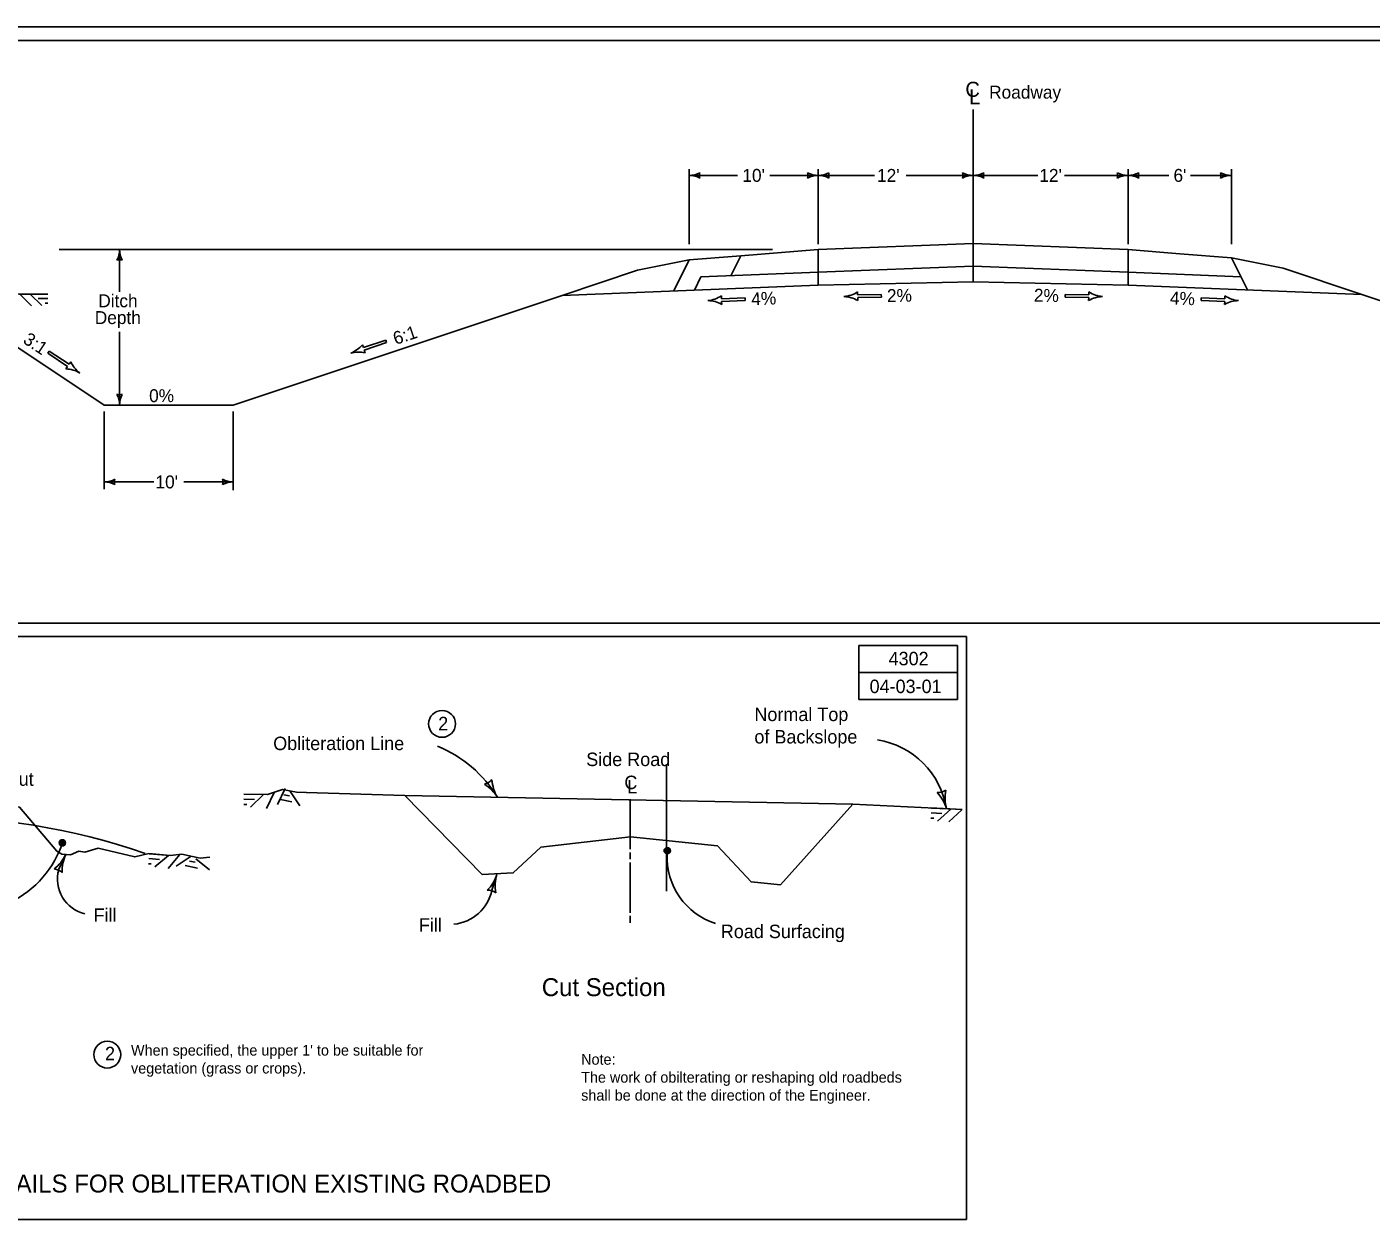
# Model space of a CAD drawing. Extents: x 4574 to 81668, y 5908 to 13780.
# Drawn here: x 10645 to 12144, y 8607 to 9944 of the extents above; entities that cross this region are included whole.
import ezdxf

# ---------------------------------------------------------------- set-up
doc = ezdxf.new("R2010")
doc.units = 0
for name, color, linetype in [('Cell', 7, 'Continuous'), ('dsnCellElements', 7, 'Continuous'), ('DsnShtRevisedText', 7, 'Continuous'), ('dsnStdBorder', 7, 'Continuous'), ('dsnStdLabel', 7, 'Continuous'), ('dsnStdNameDate', 7, 'Continuous'), ('dsnTextFinalPlan', 7, 'Continuous'), ('dsnTextTabulation', 7, 'Continuous'), ('dsnXsExistingGround', 7, 'Continuous'), ('dsnXsShldrGranularBottom', 7, 'Continuous'), ('dsnXsShldrHMABottom', 7, 'Continuous'), ('dsnXsShldrSpecialBackBottom', 7, 'Continuous'), ('dsnXsSubgrPara', 7, 'Continuous'), ('Level 11', 7, 'Continuous'), ('Level 6', 7, 'Continuous'), ('Level 7', 7, 'Continuous'), ('Level 8', 7, 'Continuous'), ('SheetAddendum', 7, 'Continuous'), ('SheetBorder', 7, 'Continuous'), ('ShtPlotIdentification', 7, 'Continuous'), ('TL_ExistingPvmtBtm', 7, 'Continuous'), ('TL_ExistingPvmtTop', 7, 'Continuous')]:
    doc.layers.add(name, color=color, linetype=linetype)

msp = doc.modelspace()

# ---------------------------------------------------------------- linework, layer by layer
at = {"layer": 'Cell'}
for p, q in [((11325.7, 9672.5), (11241.8, 9644.6)), ((11383.3, 9684.1), (11325.7, 9672.5)), ((11241.8, 9644.6), (10874.9, 9522.2)), ((12133.5, 9645.5), (12285.8, 9594.8)), ((10730.9, 9522.2), (10559, 9636.8)), ((10874.9, 9522.2), (10730.9, 9522.2))]:
    msp.add_line(p, q, dxfattribs=at)
at = {"layer": 'dsnCellElements'}
for p, q in [((11358, 9121.6), (11358, 8980.1)), ((10680.1, 9003.9), (10688, 9021)), ((11163.3, 8981.1), (11168.8, 8998.8))]:
    msp.add_line(p, q, dxfattribs=at)
for points in [[(10886.8, 9088.1), (10913.2, 9087.8), (10929.8, 9093.5), (10945.5, 9090.4), (10956, 9090.1)], [(10886.8, 9088.1), (10913.2, 9087.8), (10929.8, 9093.5), (10945.5, 9090.4), (10956.5, 9090.1)], [(10886.8, 9088.1), (10913.2, 9087.8), (10929.8, 9093.5), (10945.5, 9090.4), (10954.8, 9090.1)], [(10956, 9090.1), (11066, 9086.7), (11152.4, 8998.5), (11187.1, 9000.5), (11217.9, 9029), (11317.8, 9040.7), (11414.7, 9030.8), (11452.3, 8990.4), (11485.2, 8987.3), (11565.8, 9077.3), (11687.7, 9071.1)], [(10267.7, 9010.1), (10268.5, 9010.6), (10279.4, 9008.9), (10318.4, 9017.9), (10338, 9011), (10384.6, 9020), (10443.1, 9071.5), (10537.4, 9080.9), (10636.5, 9073.7), (10678.1, 9024.7), (10683.8, 9021.3), (10693.5, 9020.7), (10702.5, 9024.7), (10709.2, 9023.7), (10724, 9028.2), (10764.9, 9018.3), (10780.5, 9022), (10780.7, 9021.9)], [(11681.2, 9071.4), (11652.3, 9072.9)], [(11681.2, 9071.4), (11653.5, 9072.8)], [(11653.5, 9072.8), (11681.2, 9071.4)], [(10780.5, 9022), (10804.3, 9019.9), (10817.4, 9021.2), (10838, 9016.8), (10848.7, 9017.9)], [(10781.1, 9021.9), (10804.3, 9019.9), (10817.4, 9021.2), (10838, 9016.8), (10848.7, 9017.9)]]:
    msp.add_lwpolyline(points, dxfattribs=at)
at = {"layer": 'DsnShtRevisedText'}
msp.add_line((11066, 9086.7), (11565.8, 9077.3), dxfattribs=at)
for points in [[(11317.4, 9082.7), (11317.4, 9026.9)], [(11317.4, 9023.1), (11317.4, 9015.7)], [(11317.4, 9012), (11317.4, 8956.1)], [(11317.4, 8952.4), (11317.4, 8944.9)]]:
    msp.add_lwpolyline(points, dxfattribs=at)
for centre, radius, start, end in [((10539.4, 8343.7), 718.7, 70.7273, 111.6141), ((11436.5, 9018), 77.8, 174.663, 174.8906)]:
    msp.add_arc(centre, radius, start, end, dxfattribs=at)
at = {"layer": 'dsnStdBorder'}
msp.add_lwpolyline([(10147.5, 9929), (13252.5, 9929), (13252.5, 9279), (10147.5, 9279), (10147.5, 9929)], dxfattribs=at)
at = {"layer": 'dsnStdLabel'}
for p, q in [((11419.3, 9644.1), (11419.4, 9640.8)), ((11419.4, 9640.8), (11445.8, 9641.8)), ((11445.8, 9641.8), (11445.9, 9638.9)), ((11555.8, 9643.3), (11555.8, 9643.3)), ((11571.1, 9648.4), (11571.1, 9645)), ((11571.1, 9645), (11597.5, 9645.6)), ((11597.6, 9642.7), (11571.2, 9642.1)), ((11571.2, 9642.1), (11571.2, 9638.8)), ((11597.5, 9645.6), (11597.6, 9642.7)), ((11828.9, 9645), (11802.5, 9645.6)), ((11802.5, 9645.6), (11802.5, 9642.7)), ((11802.5, 9642.7), (11828.9, 9642.1)), ((11828.9, 9642.1), (11828.8, 9638.8)), ((11829, 9648.4), (11828.9, 9645)), ((11844.2, 9643.3), (11844.2, 9643.3)), ((11954.3, 9641.8), (11954.2, 9638.9)), ((11980.7, 9640.8), (11954.3, 9641.8)), ((11980.8, 9644.1), (11980.7, 9640.8)), ((11404.2, 9638.7), (11404.2, 9638.7)), ((11445.9, 9638.9), (11419.5, 9637.9)), ((11419.5, 9637.9), (11419.6, 9634.5)), ((11954.2, 9638.9), (11980.5, 9637.9)), ((11980.5, 9637.9), (11980.4, 9634.5)), ((11995.9, 9638.7), (11995.9, 9638.7)), ((11019.9, 9586.4), (11045, 9594.7)), ((11045, 9594.7), (11045.9, 9592)), ((10669.7, 9582.4), (10668.1, 9580)), ((10668.1, 9580), (10690.1, 9565.4)), ((10691.7, 9567.8), (10669.7, 9582.4)), ((11005.9, 9580.1), (11005.9, 9580.1)), ((11018.9, 9589.5), (11019.9, 9586.4)), ((11045.9, 9592), (11020.8, 9583.6)), ((11020.8, 9583.6), (11021.9, 9580.4)), ((10690.1, 9565.4), (10688.2, 9562.6)), ((10693.6, 9570.6), (10691.7, 9567.8)), ((10703.6, 9558.1), (10703.6, 9558.1))]:
    msp.add_line(p, q, dxfattribs=at)
for centre, start, end in [((11401.6, 9669.6), 274.6426, 304.6726), ((11554, 9674.2), 273.4978, 303.5278), ((11555.2, 9612.3), 58.7638, 88.7938), ((11844.8, 9612.3), 91.2062, 121.2362), ((11846.1, 9674.2), 236.4722, 266.5022), ((11998.4, 9669.6), 235.3274, 265.3574), ((11404.1, 9607.8), 59.9086, 89.9386), ((11995.9, 9607.8), 90.0614, 120.0914), ((10994.9, 9609.1), 290.787, 320.817), ((11014.4, 9550.4), 76.053, 106.083), ((10721.8, 9583.1), 203.9305, 233.9606), ((10687.5, 9531.6), 58.6646, 88.6946)]:
    msp.add_arc(centre, 30.9, start, end, dxfattribs=at)
at = {"layer": 'dsnStdNameDate'}
for p, q in [((11527.2, 9656), (11527.2, 9695.6)), ((11872.8, 9695.6), (11872.8, 9656))]:
    msp.add_line(p, q, dxfattribs=at)
at = {"layer": 'dsnTextFinalPlan'}
for p, q in [((11700, 9659.6), (11700, 9851.7)), ((11383.3, 9785.4), (11383.3, 9701.8)), ((11437.3, 9778.4), (11383.3, 9778.4)), ((11527.2, 9778.4), (11473.3, 9778.4)), ((11527.2, 9785.4), (11527.2, 9701.8)), ((11589.8, 9778.4), (11527.2, 9778.4)), ((11700, 9778.4), (11625.1, 9778.4)), ((11772.3, 9778.4), (11700, 9778.4)), ((11872.8, 9778.4), (11801.8, 9778.4)), ((11872.8, 9785.4), (11872.8, 9701.8)), ((11912.4, 9778.4), (11872.8, 9778.4)), ((11912.4, 9778.4), (11918.4, 9778.4)), ((11948.4, 9778.4), (11942.4, 9778.4)), ((11988, 9778.4), (11948.4, 9778.4)), ((11988, 9785.4), (11988, 9701.8)), ((10680.6, 9695.7), (11476.1, 9695.7)), ((10748.1, 9648.7), (10748.1, 9695.7)), ((10748.1, 9522.2), (10748.1, 9604)), ((10730.9, 9515), (10730.9, 9428.4)), ((10874.9, 9515), (10874.9, 9427.5)), ((10786.1, 9436.5), (10730.9, 9436.5)), ((10874.9, 9436.5), (10819.7, 9436.5))]:
    msp.add_line(p, q, dxfattribs=at)
for centre, radius, start, end in [((11383.3, 9803.9), 25.5, 270, 298.0725), ((11383.3, 9752.9), 25.5, 61.9275, 90), ((11404.7, 9778.4), 9.85, 162.2666, 197.7334), ((11505.9, 9778.4), 9.85, 342.2667, 17.7334), ((11527.2, 9803.9), 25.5, 241.9275, 270), ((11527.2, 9752.9), 25.5, 90, 118.0725), ((11527.2, 9803.9), 25.5, 270, 298.0725), ((11527.2, 9752.9), 25.5, 61.9275, 90), ((11548.6, 9778.4), 9.85, 162.2666, 197.7334), ((11678.6, 9778.4), 9.85, 342.2667, 17.7334), ((11700, 9803.9), 25.5, 241.9275, 270), ((11700, 9752.9), 25.5, 90, 118.0725), ((11700, 9803.9), 25.5, 270, 298.0725), ((11700, 9752.9), 25.5, 61.9275, 90), ((11721.4, 9778.4), 9.85, 162.2666, 197.7334), ((11851.4, 9778.4), 9.85, 342.2667, 17.7334), ((11872.8, 9803.9), 25.5, 241.9275, 270), ((11872.8, 9752.9), 25.5, 90, 118.0725), ((11872.8, 9803.9), 25.5, 270, 298.0725), ((11872.8, 9752.9), 25.5, 61.9275, 90), ((11894.2, 9778.4), 9.85, 162.2666, 197.7334), ((11966.6, 9778.4), 9.85, 342.2667, 17.7334), ((11988, 9803.9), 25.5, 241.9275, 270), ((11988, 9752.9), 25.5, 90, 118.0725), ((10722.6, 9695.7), 25.5, 331.9275, 360), ((10773.6, 9695.7), 25.5, 180, 208.0725), ((10748.1, 9674.3), 9.85, 72.2666, 107.7334), ((10748.1, 9543.6), 9.85, 252.2666, 287.7334), ((10722.6, 9522.2), 25.5, 360, 28.0725), ((10773.6, 9522.2), 25.5, 151.9275, 180), ((10730.9, 9462), 25.5, 270, 298.0725), ((10730.9, 9411), 25.5, 61.9275, 90), ((10752.3, 9436.5), 9.85, 162.2666, 197.7334), ((10853.5, 9436.5), 9.85, 342.2666, 17.7334), ((10874.9, 9462), 25.5, 241.9275, 270), ((10874.9, 9411), 25.5, 90, 118.0725)]:
    msp.add_arc(centre, radius, start, end, dxfattribs=at)
at = {"layer": 'dsnXsExistingGround'}
for p, q in [((10637.2, 9645.6), (10650, 9633)), ((10648.4, 9645.9), (10661.2, 9633.3))]:
    msp.add_line(p, q, dxfattribs=at)
for points in [[(10667.9, 9646), (10636, 9645.8), (10604.2, 9646.8), (10557.3, 9650), (10510.6, 9655)], [(10667.9, 9641.1), (10657.1, 9641)], [(10667.9, 9635.9), (10665, 9635.9)]]:
    msp.add_lwpolyline(points, dxfattribs=at)
at = {"layer": 'dsnXsShldrGranularBottom'}
for p, q in [((11988, 9686.4), (12005.9, 9650.7)), ((11383.3, 9684.1), (11366, 9649.5))]:
    msp.add_line(p, q, dxfattribs=at)
at = {"layer": 'dsnXsShldrHMABottom'}
msp.add_line((11440.9, 9688.7), (11429.8, 9666.5), dxfattribs=at)
at = {"layer": 'dsnXsShldrSpecialBackBottom'}
msp.add_line((11396.4, 9665.1), (11389.1, 9650.4), dxfattribs=at)
at = {"layer": 'dsnXsSubgrPara'}
for p, q in [((11527.2, 9656), (11241.8, 9644.6)), ((11872.8, 9656), (12133.5, 9645.5))]:
    msp.add_line(p, q, dxfattribs=at)
msp.add_lwpolyline([(11527.2, 9656), (11700, 9659.6), (11872.8, 9656)], dxfattribs=at)
at = {"layer": 'Level 11'}
msp.add_lwpolyline([(11682.5, 9254), (11682.5, 9194), (11572.5, 9194), (11572.5, 9254), (11682.5, 9254), (11682.5, 9224), (11572.5, 9224)], dxfattribs=at)
at = {"layer": 'Level 8'}
for centre, radius, start, end in [((11578.6, 9057.2), 92.8, 9.2544, 80.8486), ((11049.9, 9012), 140, 31.313, 67.8349), ((10577.1, 9069.5), 113, 292.5261, 339.8121), ((11436.5, 9018), 77.8, 177.31, 252.2589), ((10718.8, 8993.6), 40, 165.0555, 256.3065), ((11116.2, 8991.1), 48.1, 275.6798, 348.0251)]:
    msp.add_arc(centre, radius, start, end, dxfattribs=at)
at = {"layer": 'SheetAddendum'}
for points in [[(10147.5, 9264), (11692.5, 9264), (11692.5, 8614), (10147.5, 8614), (10147.5, 9264)], [(10684, 9030.8), (10685.2, 9031.3), (10687, 9031.9), (10687.4, 9033.8), (10687.1, 9035.4), (10685.9, 9036.9), (10684.2, 9036.8), (10682.4, 9036.5), (10681.5, 9035), (10681.3, 9033.5), (10682.4, 9031.5), (10683.7, 9031.3), (10685.6, 9031.7), (10687.1, 9032.9), (10687, 9034.7), (10685.9, 9036.1), (10684.2, 9036.2), (10682.4, 9035.9), (10682.1, 9034.8), (10681.7, 9033.6), (10682.6, 9032.1), (10683.9, 9032.1), (10685.5, 9032.4), (10686.6, 9033.2), (10686, 9034.7), (10684.8, 9035.6), (10683.3, 9035.7), (10682.9, 9034.9), (10682.4, 9033.9), (10683.2, 9032.7), (10684.3, 9032.4), (10685.3, 9033), (10685.4, 9034.1), (10684.9, 9034.9), (10683.8, 9035.2), (10683.3, 9034.8), (10683, 9034.1), (10683.6, 9033.2), (10684.3, 9033.1), (10685, 9033.5), (10684.9, 9034.1), (10684.4, 9034.5), (10683.6, 9034.5), (10683.7, 9034), (10684.3, 9033.7)], [(11358.6, 9022), (11359.7, 9022.5), (11361.6, 9023.1), (11361.9, 9024.9), (11361.7, 9026.6), (11360.5, 9028.1), (11358.8, 9027.9), (11356.9, 9027.7), (11356, 9026.2), (11355.9, 9024.7), (11357, 9022.6), (11358.3, 9022.5), (11360.1, 9022.9), (11361.7, 9024.1), (11361.6, 9025.9), (11360.4, 9027.3), (11358.8, 9027.4), (11356.9, 9027.1), (11356.7, 9026), (11356.3, 9024.8), (11357.1, 9023.3), (11358.5, 9023.3), (11360, 9023.5), (11361.1, 9024.4), (11360.6, 9025.9), (11359.4, 9026.8), (11357.9, 9026.9), (11357.5, 9026), (11357, 9025.1), (11357.7, 9023.9), (11358.9, 9023.6), (11359.9, 9024.2), (11360, 9025.3), (11359.4, 9026.1), (11358.4, 9026.4), (11357.9, 9026), (11357.6, 9025.3), (11358.1, 9024.4), (11358.9, 9024.2), (11359.6, 9024.7), (11359.5, 9025.3), (11358.9, 9025.7), (11358.2, 9025.7), (11358.2, 9025.1), (11358.9, 9024.8)]]:
    msp.add_lwpolyline(points, dxfattribs=at)
for centre, radius in [((11107.7, 9166.7), 15), ((10684.3, 9034), 3.5), ((11358.8, 9025.2), 3.5), ((10734.3, 8797.8), 15)]:
    msp.add_circle(centre, radius, dxfattribs=at)
for centre, radius, start, end in [((11151, 9115.2), 16.4, 283.5797, 319.0464), ((11205.8, 9106.8), 42.5, 183.2405, 211.313), ((11133.2, 9062.7), 42.5, 31.313, 59.3855), ((11660.4, 9106.4), 16.4, 268.172, 303.6387), ((11629.3, 9060.5), 42.5, 15.9054, 43.9779), ((11711.1, 9083.8), 42.5, 167.8329, 195.9054), ((10649.3, 9038.7), 42.5, 307.3638, 335.4363), ((10726.6, 9003.4), 42.5, 155.4363, 183.5088), ((10673.2, 8988.6), 16.4, 47.7029, 83.1696), ((11128.2, 9011.4), 42.5, 314.7357, 342.8082), ((11209.4, 8986.2), 42.5, 162.8082, 190.8807), ((11158.3, 8964.8), 16.4, 55.0749, 90.5416)]:
    msp.add_arc(centre, radius, start, end, dxfattribs=at)
at = {"layer": 'SheetBorder'}
msp.add_lwpolyline([(10132.5, 9944), (13267.5, 9944), (13267.5, 7924), (10132.5, 7924)], close=True, dxfattribs=at)
at = {"layer": 'ShtPlotIdentification'}
for p, q in [((10908.4, 9087.8), (10894.1, 9073.9)), ((10920.5, 9090.1), (10911.8, 9072.1)), ((10932.7, 9094.6), (10924, 9076.6)), ((10938.1, 9091.9), (10949.2, 9075.2)), ((11675.1, 9071.7), (11660.2, 9058.3)), ((11687.5, 9070.9), (11672.7, 9057.5)), ((10802.7, 9020), (10787.4, 9007.2)), ((10815.1, 9020.8), (10802.4, 9005.3)), ((10827.8, 9019), (10811, 9008.1)), ((10833, 9016.3), (10848.5, 9003.7))]:
    msp.add_line(p, q, dxfattribs=at)
for points in [[(10931.2, 9087.7), (10937.6, 9086.4)], [(10886.6, 9076.9), (10889.9, 9076.8)], [(10886.7, 9082.6), (10898.7, 9082.5)], [(10927.6, 9082.4), (10940.2, 9079.9)], [(11652.9, 9061.6), (11656.2, 9061.4)], [(11653.2, 9067.4), (11665.2, 9066.8)], [(10780.2, 9010.7), (10783.4, 9010.4)], [(10780.7, 9016.5), (10792.6, 9015.4)], [(10826.1, 9013.7), (10832.5, 9012.4)], [(10821.1, 9008.8), (10835, 9005.8)]]:
    msp.add_lwpolyline(points, dxfattribs=at)
at = {"layer": 'TL_ExistingPvmtBtm'}
for p, q in [((11527.2, 9670.4), (11396.4, 9665.1)), ((11700, 9677.3), (11527.2, 9670.4)), ((11872.8, 9670.4), (11700, 9677.3)), ((11872.8, 9670.4), (11998.5, 9665.3))]:
    msp.add_line(p, q, dxfattribs=at)
at = {"layer": 'TL_ExistingPvmtTop'}
for p, q in [((11700, 9702.5), (11527.2, 9695.6)), ((11872.8, 9695.6), (11700, 9702.5)), ((11440.9, 9688.7), (11383.3, 9684.1)), ((11527.2, 9695.6), (11440.9, 9688.7)), ((11872.8, 9695.6), (11930.4, 9691)), ((11930.4, 9691), (11988, 9686.4)), ((11988, 9686.4), (12045.6, 9674.8)), ((12045.6, 9674.8), (12133.3, 9645.6))]:
    msp.add_line(p, q, dxfattribs=at)

# ---------------------------------------------------------------- texts
at = {"layer": 'dsnStdLabel'}
for s, p in [('C', (11691.3, 9866)), ('L', (11695.4, 9857.7))]:
    msp.add_text(s, height=16.8, dxfattribs=at).set_placement(p)
for s, rotation, p in [('4%', 2.2906, (11452.8, 9633.4)), ('2%', 1.1458, (11604, 9637)), ('2%', 358.8542, (11767.6, 9637.6)), ('4%', 357.7094, (11919.2, 9634.6)), ('6:1', 18.435, (11055.9, 9589.2)), ('3:1', 326.3126, (10639.3, 9592.3))]:
    msp.add_text(s, height=14.4, rotation=rotation, dxfattribs=at).set_placement(p)
at = {"layer": 'dsnTextFinalPlan'}
for s, p in [('Roadway', (11717.8, 9864)), ("10'", (11442.6, 9771.2)), ("12'", (11592.8, 9771.2)), ("12'", (11773.8, 9771.2)), ("6'", (11923.4, 9771.2)), ('Ditch', (10724.3, 9631.3)), ('Depth', (10720.4, 9612.6)), ('0%', (10781, 9525.5)), ("10'", (10788.1, 9429.3))]:
    msp.add_text(s, height=14.4, dxfattribs=at).set_placement(p)
at = {"layer": 'dsnTextTabulation'}
for s, p in [('4302', (11605.7, 9232)), ('04-03-01', (11584.5, 9201))]:
    msp.add_text(s, height=15, dxfattribs=at).set_placement(p)
at = {"layer": 'Level 6'}
for s, p in [('Cut Section', (11218.9, 8863)), ('TYPICAL DETAILS FOR OBLITERATION EXISTING ROADBED', (10459.7, 8644))]:
    msp.add_text(s, height=19.999, dxfattribs=at).set_placement(p)
at = {"layer": 'Level 7'}
for s, height, p in [('Normal Top ', 15, (11456, 9169.8)), ('2', 15, (11103.4, 9159.5)), ('of Backslope', 15, (11456, 9144.8)), ('Obliteration Line', 15, (10919.4, 9137.4)), ('Side Road', 15, (11268.5, 9119.6)), ('Cut', 15, (10621.1, 9097.6)), ('C', 15, (11311, 9093.9)), ('L', 15, (11314.1, 9089.2)), ('Fill', 15, (10719.1, 8945.9)), ('Fill', 15, (11081.9, 8934.8)), ('Road Surfacing', 15, (11418.6, 8927.7)), ('2', 15, (10731.8, 8791.5)), ("When specified, the upper 1' to be suitable for", 12, (10760.8, 8796.7)), ('vegetation (grass or crops).', 12, (10760.8, 8776.7)), ('Note:', 12, (11262.8, 8786.5)), ('The work of obilterating or reshaping old roadbeds ', 12, (11262.8, 8766.5)), ('shall be done at the direction of the Engineer.', 12, (11262.8, 8746.5))]:
    msp.add_text(s, height=height, dxfattribs=at).set_placement(p)

doc.saveas('drawing.dxf')
